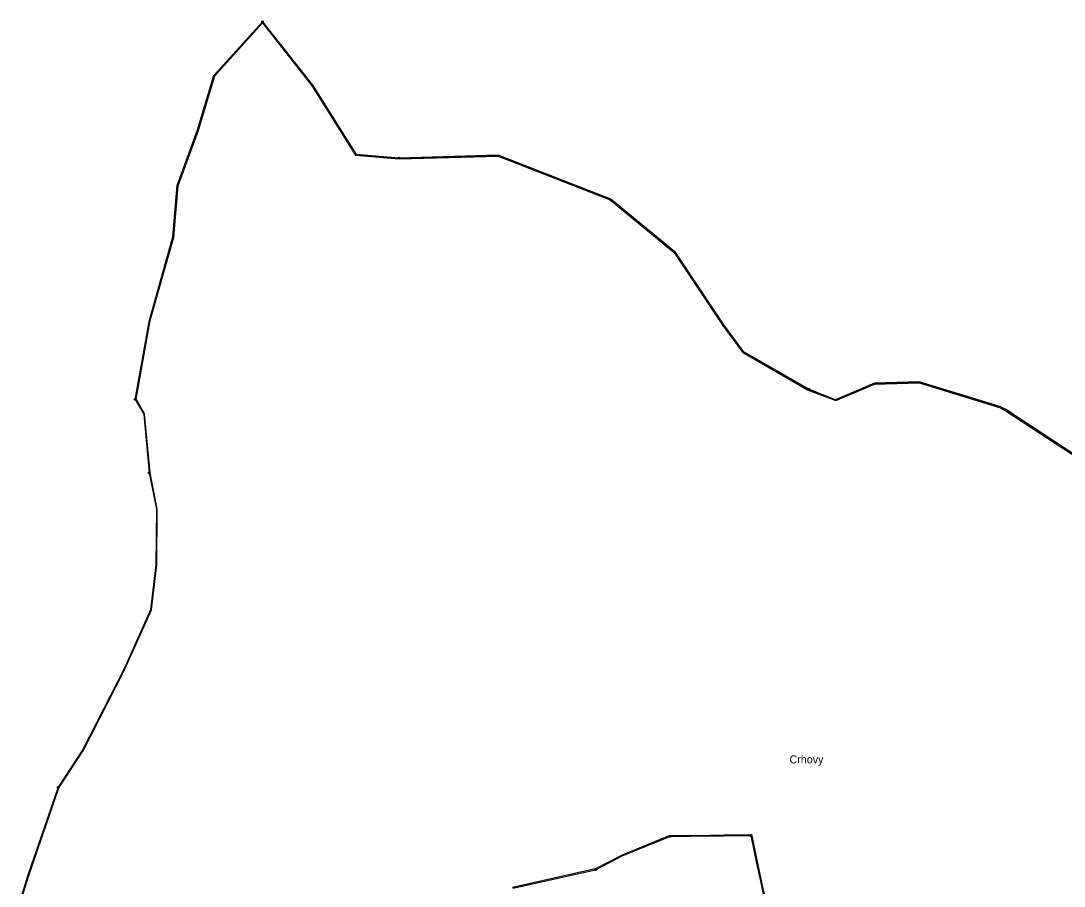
# Model space of a CAD drawing. Extents: x -652854 to -650068, y -1097661 to -1095417.
# Drawn here: x -652854 to -652280, y -1097045 to -1096569 of the extents above; entities that cross this region are included whole.
import ezdxf

# ---------------------------------------------------------------- set-up
doc = ezdxf.new("R2010")
doc.units = 0
for name, color, linetype in [('Geodetické body', 7, 'Continuous'), ('Hranice obcí', 7, 'Continuous'), ('Názvy', 7, 'Continuous'), ('Obvody jako plochy', 7, 'Continuous'), ('Ostatní hranice', 7, 'Continuous')]:
    doc.layers.add(name, color=color, linetype=linetype)

msp = doc.modelspace()

# ---------------------------------------------------------------- linework, layer by layer
at = {"layer": 'Geodetické body'}
for centre, radius in [((-652720.76, -1096569.86), 0.5), ((-652720.76, -1096569.86), 0.001), ((-652645.66, -1096644.73), 0.5), ((-652645.66, -1096644.73), 0.001), ((-652420.55, -1096771.81), 0.5), ((-652420.55, -1096771.81), 0.001), ((-652790.66, -1096777.32), 0.5), ((-652790.66, -1096777.32), 0.001), ((-652782.99, -1096817.71), 0.5), ((-652782.99, -1096817.71), 0.001), ((-652833.09, -1096990.48), 0.5), ((-652833.09, -1096990.48), 0.001), ((-652496.84, -1097017.49), 0.5), ((-652496.84, -1097017.49), 0.5), ((-652496.84, -1097017.49), 0.001), ((-652496.84, -1097017.49), 0.001), ((-652452.39, -1097016.97), 0.5), ((-652452.39, -1097016.97), 0.001), ((-652537.71, -1097035.78), 0.5), ((-652537.71, -1097035.78), 0.5), ((-652537.71, -1097035.78), 0.001), ((-652537.71, -1097035.78), 0.001)]:
    msp.add_circle(centre, radius, dxfattribs=at)
at = {"layer": 'Hranice obcí'}
for p, q in [((-652747.4, -1096599.38), (-652720.76, -1096569.86)), ((-652720.76, -1096569.86), (-652692.99, -1096604.9)), ((-652756.4, -1096629.23), (-652747.4, -1096599.38)), ((-652692.99, -1096604.9), (-652669.29, -1096642.79)), ((-652767.61, -1096659.87), (-652756.4, -1096629.23)), ((-652669.29, -1096642.79), (-652645.66, -1096644.73)), ((-652645.66, -1096644.73), (-652591.14, -1096643.22)), ((-652591.14, -1096643.22), (-652529.37, -1096667.27)), ((-652769.99, -1096688.05), (-652767.61, -1096659.87)), ((-652529.37, -1096667.27), (-652494.18, -1096696.31)), ((-652782.87, -1096733.85), (-652769.99, -1096688.05)), ((-652494.18, -1096696.31), (-652467.31, -1096736.39)), ((-652790.66, -1096777.32), (-652782.87, -1096733.85)), ((-652467.31, -1096736.39), (-652456.66, -1096750.95)), ((-652456.66, -1096750.95), (-652420.55, -1096771.81)), ((-652405.76, -1096777.53), (-652384.45, -1096768.45)), ((-652384.45, -1096768.45), (-652359.84, -1096767.69)), ((-652359.84, -1096767.69), (-652315.5, -1096781.34)), ((-652420.55, -1096771.81), (-652405.76, -1096777.53)), ((-652790.66, -1096777.32), (-652786.01, -1096785.4)), ((-652315.5, -1096781.34), (-652312.31, -1096782.98)), ((-652786.01, -1096785.4), (-652782.99, -1096817.71)), ((-652312.31, -1096782.98), (-652252.3, -1096822.35)), ((-652782.99, -1096817.71), (-652779.04, -1096837.67)), ((-652779.04, -1096837.67), (-652779.33, -1096868.2)), ((-652779.33, -1096868.2), (-652782.29, -1096892.91)), ((-652782.29, -1096892.91), (-652796.74, -1096925.4)), ((-652796.74, -1096925.4), (-652819.52, -1096969.75)), ((-652819.52, -1096969.75), (-652833.09, -1096990.48)), ((-652833.09, -1096990.48), (-652849.85, -1097039.36)), ((-652523.12, -1097028.24), (-652503.64, -1097020.27)), ((-652503.64, -1097020.27), (-652496.84, -1097017.49)), ((-652496.84, -1097017.49), (-652474.53, -1097017.23)), ((-652474.53, -1097017.23), (-652467.31, -1097017.14)), ((-652467.31, -1097017.14), (-652452.39, -1097016.97)), ((-652452.39, -1097016.97), (-652449.17, -1097032.27)), ((-652537.71, -1097035.78), (-652523.12, -1097028.24)), ((-652449.17, -1097032.27), (-652446.74, -1097043.8)), ((-652849.85, -1097039.36), (-652853.51, -1097051.15)), ((-652583.19, -1097045.97), (-652537.71, -1097035.78)), ((-652446.74, -1097043.8), (-652445.23, -1097051.01))]:
    msp.add_line(p, q, dxfattribs=at)
at = {"layer": 'Obvody jako plochy'}
for points in [[(-652252.3, -1096822.35), (-652312.31, -1096782.98), (-652315.5, -1096781.34), (-652359.84, -1096767.69), (-652384.45, -1096768.45), (-652405.76, -1096777.53), (-652420.55, -1096771.81), (-652456.66, -1096750.95), (-652467.31, -1096736.39), (-652494.18, -1096696.31), (-652529.37, -1096667.27), (-652591.14, -1096643.22), (-652645.66, -1096644.73), (-652669.29, -1096642.79), (-652692.99, -1096604.9), (-652720.76, -1096569.86), (-652747.4, -1096599.38), (-652756.4, -1096629.23), (-652767.61, -1096659.87), (-652769.99, -1096688.05), (-652782.87, -1096733.85), (-652790.66, -1096777.32), (-652786.01, -1096785.4), (-652782.99, -1096817.71), (-652779.04, -1096837.67), (-652779.33, -1096868.2), (-652782.29, -1096892.91), (-652796.74, -1096925.4), (-652819.52, -1096969.75), (-652833.09, -1096990.48), (-652849.85, -1097039.36), (-652853.51, -1097051.15)], [(-652583.19, -1097045.97), (-652537.71, -1097035.78), (-652523.12, -1097028.24), (-652503.64, -1097020.27), (-652496.84, -1097017.49), (-652474.53, -1097017.23), (-652467.31, -1097017.14), (-652452.39, -1097016.97), (-652449.17, -1097032.27), (-652446.74, -1097043.8), (-652445.23, -1097051.01)]]:
    msp.add_lwpolyline(points, dxfattribs=at)
at = {"layer": 'Ostatní hranice'}
for p, q in [((-652746.98, -1096599.65), (-652720.77, -1096570.37)), ((-652720.77, -1096570.37), (-652693.4, -1096605.2)), ((-652755.92, -1096629.37), (-652746.98, -1096599.65)), ((-652693.4, -1096605.2), (-652669.62, -1096643.18)), ((-652767.13, -1096660), (-652755.92, -1096629.37)), ((-652669.62, -1096643.18), (-652645.7, -1096645.24)), ((-652645.7, -1096645.24), (-652591.25, -1096643.72)), ((-652591.25, -1096643.72), (-652529.61, -1096667.73)), ((-652769.5, -1096688.14), (-652767.13, -1096660)), ((-652529.61, -1096667.73), (-652494.57, -1096696.63)), ((-652782.38, -1096733.97), (-652769.5, -1096688.14)), ((-652494.57, -1096696.63), (-652467.74, -1096736.66)), ((-652790.17, -1096777.25), (-652782.38, -1096733.97)), ((-652467.74, -1096736.66), (-652457.01, -1096751.33)), ((-652457.01, -1096751.33), (-652420.78, -1096772.26)), ((-652405.75, -1096778.04), (-652384.36, -1096768.95)), ((-652384.36, -1096768.95), (-652359.93, -1096768.19)), ((-652359.93, -1096768.19), (-652315.67, -1096781.83)), ((-652420.78, -1096772.26), (-652405.75, -1096778.04)), ((-652785.53, -1096785.27), (-652790.17, -1096777.25)), ((-652782.5, -1096817.63), (-652785.53, -1096785.27)), ((-652315.67, -1096781.83), (-652312.53, -1096783.44)), ((-652312.53, -1096783.44), (-652252.34, -1096822.86)), ((-652778.55, -1096837.58), (-652782.5, -1096817.63)), ((-652778.83, -1096868.26), (-652778.55, -1096837.58)), ((-652781.81, -1096893.05), (-652778.83, -1096868.26)), ((-652796.3, -1096925.63), (-652781.81, -1096893.05)), ((-652819.09, -1096970.01), (-652796.3, -1096925.63)), ((-652832.65, -1096990.72), (-652819.09, -1096970.01)), ((-652849.37, -1097039.5), (-652832.65, -1096990.72)), ((-652523.31, -1097027.77), (-652503.78, -1097019.79)), ((-652503.78, -1097019.79), (-652496.9, -1097016.98)), ((-652496.9, -1097016.98), (-652474.51, -1097016.72)), ((-652474.51, -1097016.72), (-652467.29, -1097016.63)), ((-652467.29, -1097016.63), (-652451.97, -1097016.46)), ((-652451.97, -1097016.46), (-652448.67, -1097032.16)), ((-652537.87, -1097035.31), (-652523.31, -1097027.77)), ((-652448.67, -1097032.16), (-652446.24, -1097043.71)), ((-652537.87, -1097035.31), (-652583.28, -1097045.48)), ((-652852.88, -1097050.71), (-652849.37, -1097039.5)), ((-652446.24, -1097043.71), (-652444.74, -1097050.87))]:
    msp.add_line(p, q, dxfattribs=at)

# ---------------------------------------------------------------- texts
at = {"layer": 'Názvy'}
msp.add_text('Crhovy', height=4.4, dxfattribs=at).set_placement((-652431.12, -1096977.37))

doc.saveas('drawing.dxf')
